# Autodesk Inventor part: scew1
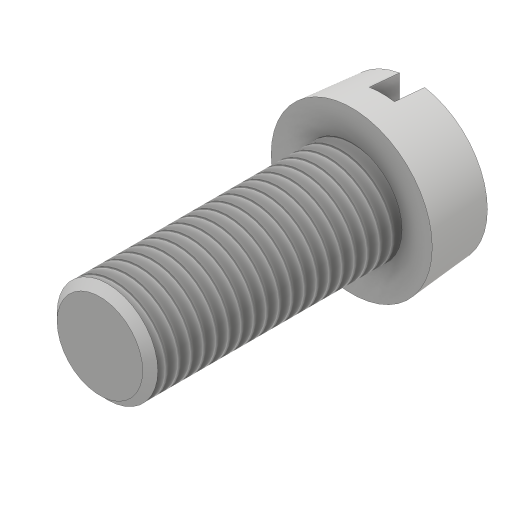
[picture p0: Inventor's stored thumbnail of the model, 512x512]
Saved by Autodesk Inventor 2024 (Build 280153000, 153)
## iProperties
Created: 2016-05
Part Number: scew1
Material: Generic
Document SubType Name: Modeling
Designer: CADCIM
Density: 1 g/cm^3
Appearance: Default
Author: CADCIM
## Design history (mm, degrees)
sketch "Sketch1"
  geometry: C1 r 9.6 at (0, 0); 1 further point
  constraints: 1 centre point, 1 coincident
  dimensions: "d0" = 19.2 diameter of C1
extrude "Extrusion1" new body sketch "Sketch1" distance "d1" = 7.2; taper "d2" = -5 deg
sketch "Sketch3"
  geometry: C1 r 6 at (0, 0); 1 further point
  constraints: 1 centre point, 1 coincident
  dimensions: "d7" = 12 diameter of C1
extrude "Extrusion3" join sketch "Sketch3" distance "d8" = 30; taper "d9" = 0 deg
thread "Thread1" dims "d13" = 10, "d14" = 0
chamfer "Chamfer2" distance "d15" = 0.9; stored, may be unused: second distance "d16" = 2, angle "d17" = 45 deg
sketch "Sketch4"
  geometry: L1 (1.5, -10.35)-(-1.5, -10.35); L2 (-1.5, -10.35)-(-1.5, 10.35); L3 (-1.5, 10.35)-(1.5, 10.35); L4 (1.5, 10.35)-(1.5, -10.35); L5 (0, -10.35)-(0, 10.35); 2 further points
  constraints: 10 end point, 3 midpoint, 2 parallel, 1 coincident, 1 horizontal, 1 perpendicular
  dimensions: "d18" = 3 distance of L1.start L1.end
extrude "Extrusion4" cut sketch "Sketch4" distance "d19" = 3.6; taper "d20" = 0 deg
body "Solid1"
